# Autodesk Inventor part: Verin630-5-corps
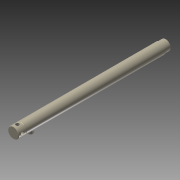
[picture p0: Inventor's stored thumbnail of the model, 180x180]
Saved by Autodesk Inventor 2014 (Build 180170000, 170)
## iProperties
Created: 2015-07
Part Number: Verin630-5-corps
Material: Générique
Document SubType Name: Modeling
Designer: OL
Density: 1 g/cm^3
Appearance: Par défaut
Author: OL
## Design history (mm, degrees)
sketch "Esquisse1"
  geometry: L1 (-18, 0)-(88.903, 0); L2 (-18, 0)-(-18, 23); L3 (-18, 23)-(-16, 25); L4 (-16, 25)-(16, 25); L5 (16, 25)-(18, 23); L6 (18, 23)-(20, 25); L7 (20, 25)-(654, 25); L8 (18, 23)-(18, 0); L9 (18, 22)-(634, 22); L10 (654, 25)-(654, 23); L11 (654, 23)-(678, 23); L12 (678, 23)-(680, 21); L13 (680, 21)-(680, 18); L14 (683, 16)-(683, 15); L15 (683, 15)-(636, 15); L16 (636, 15)-(634, 17); L17 (634, 17)-(634, 22); L18 (680, 18)-(683, 16); A1 r 5.492 centre (18, 19.886) between (20, 25) and (16, 25); 1 further point
  constraints: 36 end point, 11 perpendicular, 3 point on line, 2 parallel, 2 point on circle, 1 centre point, 1 collinear, 1 horizontal
  dimensions: "d0" = 25 distance between parallel lines of L1 L4; "d2" = 18 distance from line of L2 point (0, 0); "d3" = 18 distance from line of L8 point (0, 0); "d4" = 2 horizontal distance of L4.end L5.end; "d5" = 2 horizontal distance of L4.end L5.end; "d6" = 23 distance of L1.start L2.end; "d7" = 22 distance between parallel lines of L1 L9; "d8" = 25 distance between parallel lines of L1 L7; "d9" = 680 distance from line of L13 point (0, 0); "d10" = 0 distance from line of L1 point (0, 0); "d11" = 616 distance between parallel lines of L17 L8; "d12" = 2 distance between parallel lines of L7 L11; "d13" = 2 horizontal distance of L11.end L12.end; "d14" = 15 distance between parallel lines of L1 L15; "d15" = 2 horizontal distance of L15.end L16.end; "d16" = 2 horizontal distance of L15.end L16.end; "d17" = 20 distance between parallel lines of L10 L17; "d18" = 3 horizontal distance of L13.end L14.start; "d19" = 7 distance from line of L7 L13.end; "d20" = 2 vertical distance of L13.end L14.start
revolve "Révolution1" sketch "Esquisse1" stored, may be unused: angle "d21" = 90 deg
sketch "Esquisse2"
  geometry: C1 r 8.1 at (0, 0); 1 further point
  constraints: 1 centre point, 1 coincident
  dimensions: "d22" = 16.2 diameter of C1
extrude "Extrusion1" cut sketch "Esquisse2" stored distance "d24" = 50; taper "d25" = 0 deg
sketch "Esquisse4"
  geometry: C1 r 8.363 at (0, 0); 1 further point
  constraints: 1 centre point, 1 coincident
extrude "Extrusion2" cut sketch "Esquisse4" stored distance "d36" = 2; taper "d37" = 0 deg
sketch "Esquisse5"
  geometry: L1 (47.5, -18.6)-(52.5, -18.6); L2 (52.5, -18.6)-(52.5, -36.6); L3 (52.5, -36.6)-(47.5, -36.6); L4 (47.5, -36.6)-(47.5, -18.6); L5 (60, -17.299)-(60, -65.647); L6 (0, -78.777)-(0, 13.129) reference; L7 (-12, 0)-(72, 0) reference; 1 further point
  constraints: 10 end point, 3 parallel, 1 horizontal, 1 perpendicular
  dimensions: "d38" = 60 distance between parallel lines of L5 L6; "d39" = 36.6 distance between parallel lines of L3 L7; "d40" = 12.5 distance between parallel lines of L4 L5; "d41" = 7.5 distance between parallel lines of L5 L2; "d42" = 18 distance of L3.end L1.start
revolve "Révolution3" sketch "Esquisse5" stored, may be unused: angle "d43" = 90 deg
fillet "Congé2" dims "d44" = 5
sketch "Esquisse6"
  geometry: C1 r 8 at (0, 0); 1 further point
  constraints: 1 centre point, 1 coincident
  dimensions: "d45" = 16 diameter of C1
extrude "Extrusion3" cut sketch "Esquisse6" stored distance "d47" = 50; taper "d48" = 0 deg
node "Solide1"
